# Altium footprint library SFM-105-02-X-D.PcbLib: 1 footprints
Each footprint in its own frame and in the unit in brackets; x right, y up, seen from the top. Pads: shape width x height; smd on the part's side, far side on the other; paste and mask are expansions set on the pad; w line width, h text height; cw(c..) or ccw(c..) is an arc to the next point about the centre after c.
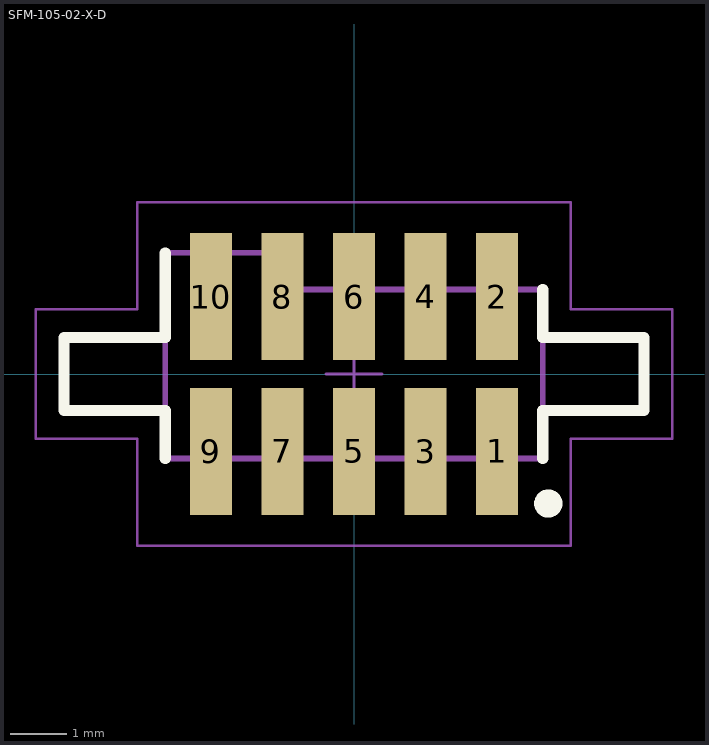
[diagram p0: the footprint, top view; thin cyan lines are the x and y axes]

## SFM-105-02-X-D [mm] "1.27mm pitch, 10 pin, socket strip; SMT"
height 4.57
pads (10):
  rect 0.75x2.25 smd mask+0: 1(2.54,-1.375) 2(2.54,1.375) 3(1.27,-1.375) 4(1.27,1.375) 5(0,-1.375) 6(0,1.375) 7(-1.27,-1.375) 8(-1.27,1.375) 9(-2.54,-1.375) 10(-2.54,1.375)
Top Overlay:
  circle w0.25: c3.45,-2.3 r0.125
  lines w0.2: -3.35,-1.5 -3.35,-0.65 -5.15,-0.65 -5.15,0.65 -3.35,0.65 -3.35,2.15 ; 3.35,-1.5 3.35,-0.65 5.15,-0.65 5.15,0.65 3.35,0.65 3.35,1.5
Mechanical 12:
  lines w0.001: -5.15,-0.65 -5.15,0.65 -3.35,0.65 -3.35,2.15 -1.3,2.15 -1.3,1.5 3.35,1.5 3.35,0.65 5.15,0.65 5.15,-0.65 3.35,-0.65 3.35,-1.5 -3.35,-1.5 -3.35,-0.65 -5.15,-0.65
Mechanical 13:
  lines w0.1: -3.35,-0.65 -5.15,-0.65 -5.15,0.65 -3.35,0.65 ; 3.35,-0.65 5.15,-0.65 5.15,0.65 3.35,0.65 ; -3.35,-1.5 3.35,-1.5 3.35,1.5 -1.3,1.5 -1.3,2.15 -3.35,2.15 -3.35,-1.5
  text ".Designator" at 0,-0.127 h1.52
Mechanical 15:
  lines w0.05: -0.5,0 0.5,0 ; 0,-0.5 0,0.5 ; -5.65,-1.15 -5.65,1.15 -3.85,1.15 -3.85,3.05 3.85,3.05 3.85,1.15 5.65,1.15 5.65,-1.15 3.85,-1.15 3.85,-3.05 -3.85,-3.05 -3.85,-1.15 -5.65,-1.15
